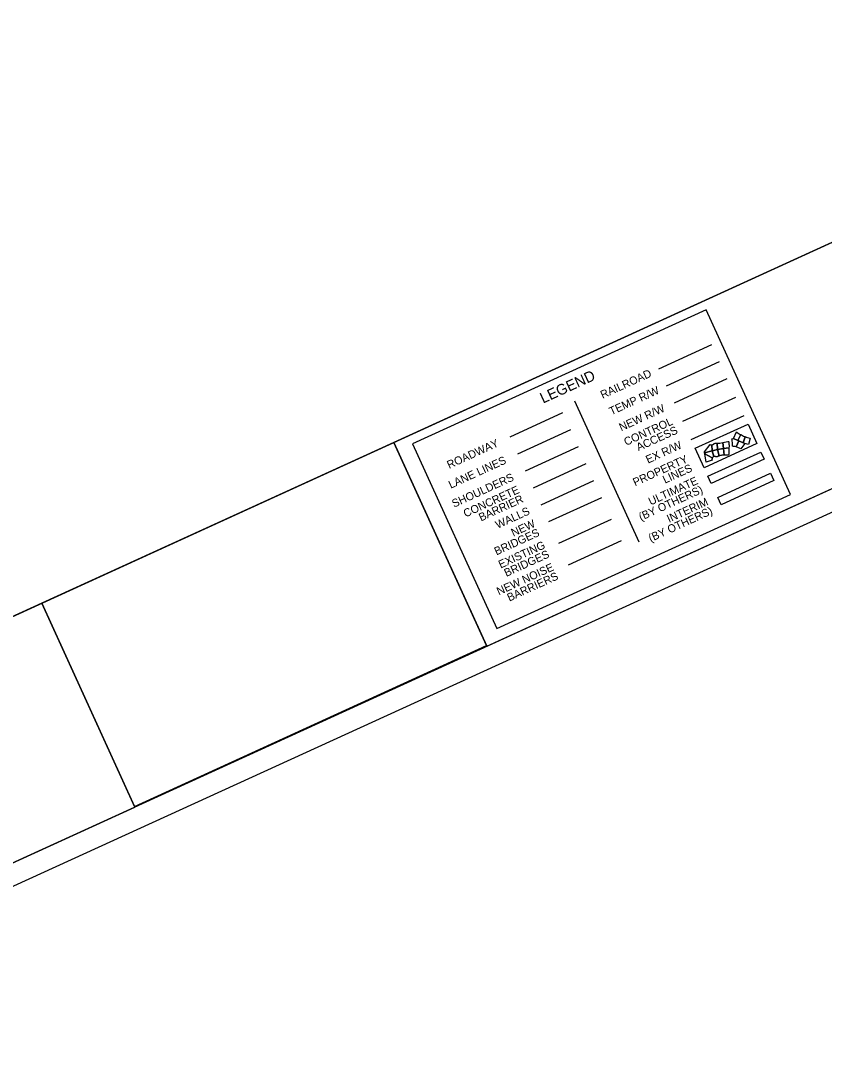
# Model space of a CAD drawing. Extents: x 1952253 to 1982336, y 791177 to 808695.
# Drawn here: x 1957087 to 1960851, y 791177 to 796057 of the extents above; entities that cross this region are included whole.
import ezdxf

# ---------------------------------------------------------------- set-up
doc = ezdxf.new("R2010")
doc.units = 0
for name, color, linetype in [('Default', 7, 'Continuous'), ('RD_SHT_Bndy', 7, 'Continuous'), ('RD_SHT_IplotShp', 7, 'Continuous'), ('RD_SHT_ShtClip', 7, 'Continuous'), ('RD_SHT_TX', 7, 'Continuous'), ('RD_Sketch1', 7, 'Continuous')]:
    doc.layers.add(name, color=color, linetype=linetype)

msp = doc.modelspace()

# ---------------------------------------------------------------- linework, layer by layer
at = {"layer": 'Default'}
for points in [[(1960440, 794130.4), (1960443.2, 794128.2), (1960448, 794124.9), (1960453, 794121.7), (1960458.1, 794118.8), (1960460.1, 794117.7), (1960446.3, 794090.3), (1960425.8, 794098.9)], [(1960460.1, 794117.7), (1960463.2, 794116), (1960468.5, 794113.4), (1960473.9, 794111), (1960479.3, 794108.8), (1960481, 794108.1), (1960471.7, 794079.6), (1960452.1, 794087.9), (1960446.3, 794090.3)], [(1960317.4, 794071.5), (1960319, 794070.6), (1960320.5, 794070), (1960322, 794069.6), (1960323.6, 794069.4), (1960325.1, 794069.4), (1960327, 794041.1), (1960290.8, 794032), (1960290, 794036.8)], [(1960333.8, 794073.7), (1960334.8, 794074.7), (1960335.9, 794075.5), (1960337.1, 794076.2), (1960338.5, 794076.7), (1960340.8, 794077.1), (1960349.6, 794077.5), (1960351.9, 794047.3), (1960327, 794041.1), (1960325.1, 794069.4), (1960327.1, 794069.7), (1960328.6, 794070.1), (1960330.1, 794070.8), (1960331.4, 794071.6), (1960332.7, 794072.6)], [(1960376.8, 794081.2), (1960379, 794051.9), (1960351.9, 794047.3), (1960349.6, 794077.5), (1960362.6, 794078.2)], [(1960405.3, 794056.2), (1960379, 794051.9), (1960376.8, 794081.2), (1960400, 794086), (1960401, 794086.1), (1960401.8, 794085.9), (1960402.6, 794085.6), (1960403.3, 794085.1), (1960403.9, 794084.4), (1960404.2, 794083.6), (1960404.4, 794082.8), (1960404.8, 794079.2), (1960405.3, 794073.5), (1960405.5, 794067.8), (1960405.6, 794062.1)], [(1960425.8, 794098.9), (1960446.3, 794090.3), (1960452.1, 794087.9), (1960439.3, 794060.2), (1960438.3, 794060.5), (1960434.1, 794061.4), (1960430, 794062.2), (1960425.8, 794062.7), (1960422.1, 794063.1), (1960422, 794069), (1960421.7, 794075), (1960421.2, 794081), (1960420.6, 794086.9), (1960419.7, 794092.9), (1960418.8, 794097.5)], [(1960452.1, 794087.9), (1960471.7, 794079.6), (1960480, 794076.8), (1960460.6, 794051.4), (1960458, 794052.9), (1960454.2, 794054.7), (1960450.3, 794056.5), (1960446.4, 794058), (1960442.4, 794059.3), (1960439.3, 794060.2)], [(1960481, 794108.1), (1960484.8, 794106.7), (1960486.1, 794106.3), (1960504.9, 794100.8), (1960496.5, 794071), (1960480, 794076.8), (1960471.7, 794079.6)], [(1960327, 794041.1), (1960334.5, 794014.7), (1960333, 794014.2), (1960331.6, 794013.5), (1960330.3, 794012.6), (1960329.2, 794011.5), (1960328.1, 794010.3), (1960327.1, 794008.8), (1960291.7, 794027), (1960290.8, 794032)], [(1960327.1, 794008.8), (1960326.5, 794007.6), (1960326, 794006.1), (1960325.7, 794004.6), (1960325.5, 794003), (1960325.6, 794001.4), (1960325.9, 793999.9), (1960326.3, 793998.4), (1960298.7, 793988), (1960291.7, 794027)], [(1960351.9, 794047.3), (1960359.3, 794018), (1960358.2, 794017.5), (1960354.9, 794016.1), (1960351.8, 794014.5), (1960351.3, 794014.3), (1960350, 794013.8), (1960348.6, 794013.5), (1960347.2, 794013.4), (1960345.8, 794013.4), (1960344.4, 794013.7), (1960343, 794014.2), (1960342.3, 794014.5), (1960340.8, 794014.9), (1960339.3, 794015.2), (1960337.7, 794015.2), (1960336.1, 794015.1), (1960334.5, 794014.7), (1960327, 794041.1)], [(1960379, 794051.9), (1960382.3, 794022), (1960380.4, 794022), (1960378.9, 794022), (1960375.4, 794021.7), (1960371.8, 794021.3), (1960368.4, 794020.6), (1960364.9, 794019.8), (1960361.5, 794018.8), (1960359.3, 794018), (1960351.9, 794047.3)], [(1960405.3, 794056.2), (1960403.8, 794024.8), (1960403.7, 794024.2), (1960403.4, 794023.3), (1960403, 794022.6), (1960402.3, 794022), (1960401.6, 794021.6), (1960400.8, 794021.3), (1960399.9, 794021.2), (1960382.3, 794022), (1960379, 794051.9)]]:
    msp.add_lwpolyline(points, close=True, dxfattribs=at)
at = {"layer": 'RD_SHT_Bndy'}
msp.add_line((1959681.1, 794275.6), (1959982.8, 793615.1), dxfattribs=at)
for points in [[(1979125.3, 802195.5), (1955294.1, 791309), (1952385.5, 797676.1), (1976216.7, 808562.6)], [(1959270.9, 793125.7), (1973897.5, 799807.4), (1973461.2, 800762.4), (1958834.7, 794080.8)], [(1959317.1, 793208.5), (1960693.8, 793837.2), (1960298.6, 794702.7), (1958921.8, 794074)], [(1960247.1, 794053.7), (1960494.7, 794166.8), (1960536.2, 794075.8), (1960288.7, 793962.7)], [(1957619.7, 792375.4), (1959269.4, 793129), (1958834.7, 794080.8), (1957185, 793327.2)], [(1955294.1, 791309), (1957621.3, 792372.1), (1957185, 793327.2), (1954857.8, 792264.1)]]:
    msp.add_lwpolyline(points, close=True, dxfattribs=at)
at = {"layer": 'RD_SHT_IplotShp'}
msp.add_lwpolyline([(1979257.8, 802146.1), (1955244.7, 791176.5), (1952253, 797725.5), (1976266.1, 808695.1)], close=True, dxfattribs=at)
at = {"layer": 'RD_SHT_ShtClip'}
msp.add_lwpolyline([(1978689, 803150.6), (1954857.8, 792264.1), (1952385.5, 797676.1), (1976216.7, 808562.6)], close=True, dxfattribs=at)
msp.add_lwpolyline([(1978689, 803150.6), (1954857.8, 792264.1), (1952385.5, 797676.1), (1976216.7, 808562.6)], close=True, dxfattribs=at)
msp.add_lwpolyline([(1978689, 803150.6), (1954857.8, 792264.1), (1952385.5, 797676.1), (1976216.7, 808562.6)], close=True, dxfattribs=at)
msp.add_lwpolyline([(1978689, 803150.6), (1954857.8, 792264.1), (1952385.5, 797676.1), (1976216.7, 808562.6)], close=True, dxfattribs=at)
at = {"layer": 'RD_Sketch1'}
for p, q in [((1960076.9, 794426.3), (1960324.5, 794539.4)), ((1960113.2, 794346.7), (1960360.8, 794459.8)), ((1960149.6, 794267.2), (1960397.2, 794380.2)), ((1960189, 794180.9), (1960436.6, 794294)), ((1959379.5, 794107.7), (1959627, 794220.8)), ((1960228.7, 794094.1), (1960476.2, 794207.2)), ((1959415.8, 794028.1), (1959663.4, 794141.2)), ((1959452.2, 793948.6), (1959699.7, 794061.6)), ((1959488.5, 793869), (1959736.1, 793982.1)), ((1959524.9, 793789.4), (1959772.5, 793902.5)), ((1959561.2, 793709.8), (1959808.8, 793822.9)), ((1959607.3, 793608.9), (1959854.9, 793722)), ((1959653.4, 793508), (1959901, 793621.1))]:
    msp.add_line(p, q, dxfattribs=at)
for points in [[(1960306.9, 793922.9), (1960554.5, 794036), (1960570.1, 794001.9), (1960322.5, 793888.7)], [(1960352.4, 793823.3), (1960600, 793936.4), (1960615.6, 793902.3), (1960368, 793789.1)]]:
    msp.add_lwpolyline(points, close=True, dxfattribs=at)

# ---------------------------------------------------------------- texts
at = {"layer": 'RD_SHT_TX'}
for s, height, rotation, p in [('LEGEND', 50, 24.5447, (1959533.9, 794262.7)), ('RAILROAD', 37.5, 24.5517, (1959813.1, 794285.2)), ('TEMP R/W', 37.5, 24.5517, (1959854, 794207.7)), ('NEW R/W ', 37.5, 24.5517, (1959900.5, 794132.8)), ('CONTROL', 37.5, 24.5517, (1959923.3, 794064.6)), ('ACCESS', 37.5, 24.5517, (1959981.4, 794039.6)), ('ROADWAY', 37.5, 24.5517, (1959094.1, 793956.8)), ('EX R/W ', 37.5, 24.5517, (1960025.7, 793981.3)), ('PROPERTY ', 37.5, 24.5517, (1959965.3, 793875.1)), ('LANE LINES', 37.5, 24.5517, (1959101.4, 793863.9)), ('LINES', 37.5, 24.5517, (1960105.1, 793887.4)), ('SHOULDERS', 37.5, 24.5517, (1959117.2, 793774.9)), ('ULTIMATE', 37.5, 24.5517, (1960038.3, 793785.2)), ('CONCRETE', 37.5, 24.5517, (1959170.9, 793729)), ('(BY OTHERS)', 37.5, 24.5517, (1959992.8, 793712.8)), ('BARRIER', 37.5, 24.5517, (1959243.2, 793710.5)), ('INTERIM', 37.5, 24.5517, (1960124.4, 793704.1)), ('WALLS', 37.5, 24.5517, (1959321.2, 793675.7)), ('(BY OTHERS)', 37.5, 24.5517, (1960038.3, 793613.3)), ('NEW', 37.5, 24.5517, (1959394.8, 793638.9)), ('BRIDGES', 37.5, 24.5517, (1959315.8, 793551.3)), ('EXISTING', 37.5, 24.5517, (1959335.4, 793489.8)), ('BRIDGES', 37.5, 24.5517, (1959361.9, 793450.4)), ('NEW NOISE', 37.5, 24.5517, (1959327, 793363.9)), ('BARRIERS', 37.5, 24.5517, (1959376, 793334.8))]:
    msp.add_text(s, height=height, rotation=rotation, dxfattribs=at).set_placement(p)

doc.saveas('drawing.dxf')
